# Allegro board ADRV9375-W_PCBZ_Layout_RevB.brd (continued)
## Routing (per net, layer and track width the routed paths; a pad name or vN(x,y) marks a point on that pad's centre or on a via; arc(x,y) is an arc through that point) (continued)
SPI_CLK: length 112.3
  TOP w0.254: U405.3 120.14,60.64 121.68,59.1 121.68,58.09 120.48,56.9 TP802.1 ; U101.K9 v6(36.44,48.38)
  TOP w0.305: R804.1 131.17,56.17 129.9,54.91 121.34,54.91 TP802.1
  L7_SIG w0.114: v8(92.85,57.96) 93.1,58.21 100.72,58.21 104.66,54.28 119,54.28 TP802.1
  L8_SIG w0.114: v6(36.44,48.38) 36.69,48.38 37.08,47.99 41.22,47.99 41.41,48.18 46,48.18 47.19,49.37 49.84,49.37 50.68,50.21 65.67,50.21 73.42,57.96 v8(92.85,57.96)
SPI_CLK_9528: length 44.4
  TOP w0.203: v1(119.77,66.09) 120.14,66.45 U405.12
  L7_SIG w0.114: v1(119.77,66.09) 119.35,66.51 119.35,66.51 119.05,66.81 119.05,66.81 119.01,66.85 118.75,66.85 116.28,69.33 96.08,69.33 93.74,71.67 84.47,71.67 83.56,70.76 82.44,70.76 v1(82.21,70.99)
  BOTTOM w0.254: U401.22 83.47,70.83 83.38,70.74 82.46,70.74 v1(82.21,70.99)
SPI_CS0: length 120.1
  TOP w0.254: v2(139.1,55.57) 138.89,55.57 138.55,55.23 R808.2 R811.1 ; U403.7 116.71,60.56 117.33,59.94 118.65,59.94 119.9,58.69 TP813.1 ; U101.K10 v6(36.44,49.18)
  L7_SIG w0.114: TP813.1 119.34,57.54 116.88,57.54 115.13,55.8 105.67,55.8 101.86,59.61 89.42,59.61 v8(89.04,59.23)
  L8_SIG w0.114: v8(89.04,59.23) 86.37,59.23 85.35,60.24 72.27,60.24 63.89,51.86 46.85,51.86 45.2,50.21 43.9,50.21 43.61,49.93 43.27,49.93 43.11,50.08 40.52,50.08 40.01,49.58 36.84,49.58 v6(36.44,49.18)
  L8_SIG w0.254: TP813.1 122.99,56.18 138.49,56.18 v2(139.1,55.57)
SPI_CS1: length 37
  TOP w0.254: 121.44,63.18 U405.5 ; 117.48,64.82 117.21,64.54 U403.1
  TOP w0.305: R812.1 R809.2 138.55,52.71 138.21,52.37 137.5,52.37 137.12,52.75 137.12,62.12 136.69,62.56 130.74,62.56 130.41,62.23 127.52,62.23 127.34,62.4 TP814.1 124.09,63.67 121.93,63.67 121.44,63.18 119.58,65.03 117.7,65.03 117.48,64.82
SPI_CS_9528: length 47
  TOP w0.203: v1(121.68,65.83) 121.44,66.07 U405.10
  L7_SIG w0.114: v1(121.68,65.83) 121.04,65.2 118.75,65.2 115.77,68.18 95.2,68.18 93.12,70.25 v1(81.7,70.25)
  BOTTOM w0.254: U401.21 83.78,70.33 83.69,70.33 83.62,70.25 v1(81.7,70.25)
SPI_DIN: length 114.3
  TOP w0.254: TP801.1 123,58.66 120.79,60.88 U405.4 ; U101.J9 v6(35.64,48.38)
  TOP w0.305: TP801.1 125.39,56.68 129.45,56.68 130.14,57.37 R805.1
  L7_SIG w0.114: TP801.1 122.03,60.03 117.4,60.03 113.93,56.56 106.18,56.56 102.24,60.5 96.97,60.5 96.59,60.88 87.6,60.88 87.6,60.89 87.17,60.89 87.17,60.88 85.56,60.88 84.03,59.36 v1(83.96,59.36)
  L8_SIG w0.114: v6(35.64,48.38) 36.03,48.76 40.34,48.76 40.95,49.37 45.27,49.37 47,51.1 64.65,51.1 72.96,59.4 83.91,59.4 v1(83.96,59.36)
SPI_DIN_9528: length 43.6
  TOP w0.203: U405.11 v1(120.79,66.34)
  L7_SIG w0.114: v1(83.28,71.33) 85.02,73.07 93.86,73.07 96.53,70.4 116.85,70.4 120.79,66.47 v1(120.79,66.34)
  BOTTOM w0.254: U401.23 83.68,71.33 v1(83.28,71.33)
SPI_DOUT: length 31.6
  TOP w0.203: TP809.1 117.59,58.69 ; 116.2,61.33 U403.6
  TOP w0.254: R806.1 136.06,55.72 136.06,55.71 136.06,55.45 135.47,54.86 130.95,54.86 130.23,54.15 119.47,54.15 118.66,54.96 118.66,57.62 116.19,60.09 116.19,61.32 116.21,61.35 U403.3
SPI_DOUT_9370: length 91.9
  TOP w0.254: U101.J10 v6(35.64,49.18) ; TP402.1 116.07,57.26 R427.2
  L7_SIG w0.097: 39.89,46.39 39.49,46.39
  L7_SIG w0.114: v1(79.64,50.08) 79.64,49.81 77.63,47.8 77.1,47.8 75.41,46.11 48.61,46.11 48.52,46.19 45.18,46.19 44.45,46.92 43.41,46.92 42.88,46.39 39.89,46.39 ; v6(35.64,49.18) 35.64,49.13 36.1,48.66 36.1,48.24 36.3,48.04 36.55,48.04 36.85,47.74 36.85,47.42 37.08,47.19 37.58,47.19 37.7,47.06 37.7,46.64 37.95,46.39 39.49,46.39
  BOTTOM w0.394: TP402.1 111.83,50.08 v1(79.64,50.08)
SPI_DOUT_9528: length 40.5
  TOP w0.254: TP401.1 101.36,71.17 111.83,71.17 R426.2
  L7_SIG w0.114: v1(82.56,71.65) 85.25,74.34 94.12,74.34 96.91,71.55 TP401.1
  BOTTOM w0.254: v1(82.56,71.65) 82.83,71.91 83.59,71.91 83.67,71.83 83.81,71.83 U401.24
STATUS_0: length 25.1
  L5_SIG w0.114: v1(96.53,79.96) 96.19,80.3 77.85,80.3 v1(77.25,79.7)
  BOTTOM w0.254: v1(96.53,79.96) 95.9,79.32 95.9,78.92 94.81,77.83 U401.55 ; R418.1 97.17,79.96
  BOTTOM w0.305: U402.1 76.63,79.69 76.64,79.7 v1(77.25,79.7)
  BOTTOM w0.394: 97.17,79.96 v1(96.53,79.96)
STATUS_1: length 24.5
  L5_SIG w0.114: v1(96.53,78.89) 77.76,78.89 v1(77.25,78.38)
  BOTTOM w0.203: R419.1 97.17,78.89
  BOTTOM w0.254: v1(96.53,78.89) 96.53,78.83 95.03,77.33 U401.56
  BOTTOM w0.305: U402.3 76.63,78.39 76.64,78.38 v1(77.25,78.38)
  BOTTOM w0.394: 97.17,78.89 v1(96.53,78.89)
SYNCINB0+: length 150.5
  TOP w0.254: U101.M4 v6(38.04,43.58)
  L7_SIG w0.091: v2(136.56,61.85) 137.02,61.39 143.14,61.39 143.75,60.77 143.75,42.43 141.97,40.65 141.36,40.65 139.91,39.2 139.91,36.09 137.78,33.96 136.77,33.96 132.45,29.64 127.77,29.64 127.14,29 ; v6(38.04,43.58) 38.04,43.25 37.71,42.91 37.71,41.85 37.93,41.62 39.84,41.62 40.77,40.68 44.84,40.68 48.14,37.38 59.68,37.38 60.57,38.27 105.19,38.27 110.14,33.32 111.79,33.32 113.19,31.92 116.24,31.92 119.66,28.49 126.63,28.49 127.14,29 ; TP807.1 127.14,29
  BOTTOM w0.203: P801.G9 v2(136.56,61.85)
SYNCINB0-: length 150.5
  TOP w0.254: U101.M3 v6(38.04,42.78)
  L7_SIG w0.091: TP808.1 126.14,29.99 126.89,29.24 127.02,29.24 ; 127.02,29.24 127.67,29.89 132.34,29.89 136.66,34.21 137.68,34.21 139.66,36.19 139.66,39.31 141.26,40.91 141.87,40.91 143.5,42.54 143.5,60.67 143.03,61.14 136.92,61.14 136.66,61.39 135.9,61.39 135.77,61.26 135.77,60.58 135.9,60.45 136.44,60.45 136.56,60.58 v2(136.56,60.58) ; 127.02,29.24 126.96,29.18 126.96,29.18 126.52,28.75 119.77,28.75 116.34,32.18 113.29,32.18 111.9,33.57 110.25,33.57 105.29,38.53 60.46,38.53 59.57,37.64 48.25,37.64 44.95,40.94 40.87,40.94 40.09,41.72 40.09,42.16 39.93,42.32 38.14,42.32 38.04,42.42 v6(38.04,42.78)
  BOTTOM w0.203: P801.G10 v2(136.56,60.58)
SYNCINB1+: length 108.7
  TOP w0.254: U101.L4 v6(37.24,43.58)
  L7_SIG w0.091: v6(37.24,43.58) 37.33,43.66 37.33,43.78 37.66,44.12 37.66,44.46 37.9,44.7 38.17,44.7 38.36,44.51 38.36,44.24 38.62,43.98 39.77,43.98 40.01,43.73 44.05,43.73 46.08,41.7 48.4,41.7 49.54,40.56 105.28,40.56 108.88,36.96 109.02,36.96 111.01,34.97 113.4,34.97 114.54,33.83 115.71,33.83 116.02,34.14 ; 116.02,34.14 116.02,34.28 TP810.1 ; 116.02,34.14 121.19,39.32 124.82,39.32 125.02,39.12 125.79,39.12 126.42,39.75 134.79,39.75 v2(135.29,40.26)
  BOTTOM w0.203: P801.G27 v2(135.29,40.26)
SYNCINB1-: length 108.8
  TOP w0.254: U101.L3 v6(37.24,42.78)
  L7_SIG w0.091: 116.84,34.6 115.81,33.57 114.44,33.57 113.29,34.72 110.9,34.72 108.92,36.7 108.78,36.7 105.18,40.31 49.43,40.31 48.29,41.45 45.98,41.45 43.95,43.48 40.01,43.48 39.76,43.23 38.73,43.23 38.51,43.44 38.51,43.56 38.17,43.9 37.8,43.9 37.58,43.68 37.58,43.46 37.56,43.44 37.56,43.44 37.24,43.12 v6(37.24,42.78) ; 116.84,34.6 121.3,39.06 124.71,39.06 124.91,38.86 125.9,38.86 126.53,39.5 134.79,39.5 v2(135.29,38.99) ; 116.84,34.6 117.55,33.89 TP811.1
  BOTTOM w0.203: P801.G28 v2(135.29,38.99)
SYNCOUTB0+: length 115.2
  TOP w0.203: U101.M13 v6(37.24,51.58)
  L8_SIG w0.091: v2(134.02,65.67) 133.55,65.2 127.9,65.2 ; v6(37.24,51.58) 37.38,51.58 37.54,51.74 37.54,52.05 37.78,52.29 38.42,52.29 38.72,51.99 39.88,51.99 40.19,51.68 44.15,51.68 45.86,53.39 51.57,53.39 58.56,60.37 70.39,60.37 71.64,61.62 71.64,66.21 76.08,70.66 76.08,71.42 77.23,72.56 84.34,72.56 86.75,70.15 120.53,70.15 125.49,65.2 127.9,65.2 ; 127.9,65.2 127.9,66.26 TP805.1
  BOTTOM w0.203: P801.H7 134.02,65.66 v2(134.02,65.67)
SYNCOUTB0-: length 115.3
  TOP w0.203: U101.M14 v6(38.04,51.58)
  L8_SIG w0.091: 127.9,64.94 127.9,63.79 TP806.1 ; 127.9,64.94 133.43,64.94 v2(134.02,64.35) ; 127.9,64.94 125.38,64.94 120.43,69.9 86.64,69.9 84.23,72.31 77.33,72.31 76.34,71.32 76.34,70.55 71.89,66.11 71.89,61.51 70.49,60.12 58.66,60.12 51.68,53.13 45.96,53.13 44.26,51.43 40.14,51.43 39.94,51.23 38.67,51.23 38.46,51.43 38.46,51.88 38.32,52.03 37.89,52.03 37.8,51.94 37.8,51.74 37.96,51.58 v6(38.04,51.58)
  BOTTOM w0.203: v2(134.02,64.35) 134.06,64.35 P801.H8
SYSREF_IN+: length 78.5
  TOP w0.254: U101.K3 v6(36.44,42.78)
  L7_SIG w0.091: v1(75.02,75.37) 75.3,75.65 75.56,75.65 75.83,75.38 75.83,74.7 75.47,74.34 73.33,74.34 72.29,73.31 72.29,73.09 70.11,70.91 66.02,70.91 64.62,69.52 59.59,69.52 58.32,68.25 48.9,68.25 46.75,66.09 46.75,65.57 43.19,62.02 43.19,58.7 41.05,56.56 39.87,56.56 37.58,54.28 35.7,54.28 32.65,51.23 32.65,50.47 32.91,50.2 32.91,49.84 33.1,49.65 33.34,49.65 33.71,49.28 33.71,49.07 33.9,48.88 34.23,48.88 34.51,48.6 34.51,45.74 34.68,45.57 34.68,43.95 35.38,43.25 35.96,43.25 v6(36.44,42.78)
  BOTTOM w0.203: 80.57,75.6 75.25,75.6 v1(75.02,75.37) ; 80.57,75.6 R424.2 ; 80.57,75.6 81.12,75.6 82.81,73.9 83.61,73.9 83.68,73.83 84.06,73.83 U401.28
SYSREF_IN-: length 78.7
  TOP w0.254: U101.K4 v6(36.44,43.58)
  L7_SIG w0.091: v6(36.44,43.58) 36.44,43.82 36.36,43.9 35.09,43.9 34.93,44.06 34.93,45.51 35.19,45.77 35.19,48.49 34.97,48.7 34.77,48.7 34.36,49.11 34.36,49.34 34.17,49.53 33.94,49.53 33.56,49.91 33.56,50.11 33.37,50.3 33.17,50.3 32.9,50.57 32.9,51.12 35.8,54.02 37.69,54.02 39.98,56.31 41.16,56.31 43.44,58.59 43.44,61.91 47,65.47 47,65.98 49.01,67.99 58.43,67.99 59.7,69.26 64.73,69.26 66.12,70.66 70.22,70.66 72.55,72.99 72.55,73.2 73.43,74.09 75.57,74.09 76.08,74.6 76.08,75.48 75.67,75.9 75.3,75.9 v1(75.02,76.18)
  BOTTOM w0.203: R424.1 80.57,75.95 ; 80.57,75.95 81.27,75.95 82.96,74.26 83.58,74.26 83.66,74.33 84.12,74.33 U401.29 ; 80.57,75.95 75.25,75.95 v1(75.02,76.18)
TEST: length 169
  TOP w0.254: U101.J6 v6(35.64,45.98)
  TOP w0.394: R504.1 R503.2 143.55,24.35 144.95,25.75 144.95,33.16 143.61,34.5 143.61,40.79 142.12,42.27 142.12,43.33 140.98,44.48 140.98,51.16 142.34,52.52 142.34,58.59 v2(141.62,59.31) 141.31,59.61 R810.1
  L7_SIG w0.114: v6(35.64,45.98) 35.97,45.64 37.47,45.64 37.73,45.89 38.44,45.89 38.7,45.64 45.73,45.64 46.87,44.5 51.55,44.5 51.68,44.63 53.22,44.63 53.86,43.99 54.49,43.99 54.5,44 76.11,44 79.44,47.32 79.8,47.32 82.56,50.08 82.56,51.97 83.34,52.75 84.21,52.75 85.13,53.67 85.13,54.55 86.26,55.67 87.64,55.67 89,57.03 100.63,57.03 104.15,53.51 121.76,53.51 127.39,59.15 133.31,59.15 133.67,58.79 141.1,58.79 v2(141.62,59.31)
TRI_STATE: length 5.4
  BOTTOM w0.394: R408.1 R409.2 122.29,73.9 122.22,73.96 Y402.2 Y401.2
TX1_ENABLE: length 58.8
  TOP w0.254: U101.M6 v6(38.04,45.18)
  TOP w0.305: P501.9 73.61,65.01 R507.1
  L5_SIG w0.114: v6(38.04,45.18) 37.7,45.51 37.22,45.51 36.77,45.96 36.77,46.95 36.49,47.24 36.3,47.24 36.1,47.44 36.1,51.72 36.39,52 36.58,52 36.77,52.2 36.77,52.52 36.65,52.64 36.65,53.7 37.54,54.59 39.7,54.59 40.56,55.45 40.56,55.45 41.73,56.63 43.58,56.63 44.06,57.1 44.48,57.1 44.74,56.85 69.51,56.85 72.53,59.86 72.53,63.8 P501.9
  BOTTOM w0.203: 73.67,66.42 P501.9
TX2_ENABLE: length 53
  TOP w0.254: U101.M8 v6(38.04,47.58)
  TOP w0.305: R506.1 73.73,62.34 P501.10
  L5_SIG w0.114: v6(38.04,47.58) 37.79,47.58 37.37,47.99 37.08,47.99 36.84,48.23 36.84,51.65 37.1,51.91 37.11,51.91 37.22,52.03 37.22,52.69 37.14,52.78 37.14,53.59 37.69,54.14 40.13,54.14 41.16,55.16 44.46,55.16 44.84,55.55 68.97,55.55 73.67,60.24 P501.10
  BOTTOM w0.203: 73.67,60.93 P501.10
TX_EXTLO+: length 12
  TOP w0.203: U101.E12 v6(32.44,49.98)
  L10_SIG w0.091: v6(32.44,49.98) arc(31.87,50.21) 31.64,50.78 arc(31.58,51.07) 31.41,51.32 31.27,51.47 arc(31.23,51.52) 31.22,51.58 arc(31.11,51.85) 30.84,51.96 30.71,51.96 arc(30.61,51.98) 30.51,52.04 arc(30.31,52.3) 30.18,52.59 arc(29.85,53.93) 29.71,55.29 arc(29.6,56.43) 29.37,57.55 arc(29.32,57.79) 29.31,58.05 arc(29.28,58.49) 29.17,58.91 arc(29.1,59.21) v5(29.14,59.52)
  BOTTOM w0.203: C336.2 v5(29.14,59.52)
TX_EXTLO-: length 11.9
  TOP w0.203: U101.E11 v6(31.64,49.98)
  L10_SIG w0.091: v6(31.64,49.98) 31.5,49.98 arc(31.42,50.01) 31.39,50.08 31.38,50.77 arc(31.38,50.77) 31.38,50.78 arc(31.34,50.97) 31.23,51.14 31.21,51.16 arc(31.16,51.19) 31.11,51.2 30.82,51.2 arc(30.59,51.3) 30.49,51.53 arc(30.46,51.69) 30.37,51.83 30.34,51.86 arc(30.1,52.16) 29.93,52.51 arc(29.6,53.88) 29.45,55.28 arc(29.35,56.39) 29.12,57.48 arc(29.07,57.77) 29.06,58.05 arc(29.01,58.58) 28.81,59.07 arc(28.57,59.25) v5(28.28,59.21)
  BOTTOM w0.203: C337.2 v5(28.28,59.21)
UNNAMED_3_CAP_I11_N1: length 11.7
  TOP w0.394: 10.81,55.05 R201.1 ; 10.81,55.05 C200.1 ; 10.81,55.05 9.6,56.26 arc(6.36,58.42) 2.55,59.18 J200.1
UNNAMED_3_CAP_I25_N1: length 12.9
  TOP w0.394: R209.1 C208.1 arc(9.56,36.55) 6.55,35.31 J201.1
UNNAMED_3_CAP_I39_N1: length 6.2
  BOTTOM w0.305: L218.2 23.74,19.6
  BOTTOM w0.394: 23.74,19.6 C217.1 arc(22.87,18.16) 22.58,17.7 arc(22.06,16.48) 21.88,15.16 arc(21.88,14.56) J202.1
UNNAMED_3_CAP_I54_N1: length 18.4
  BOTTOM w0.254: L226.2 16.82,64.82
  BOTTOM w0.394: J203.1 7.95,71.12 arc(12.91,69.69) C225.1 16.82,64.82
UNNAMED_3_CAP_I67_N1: length 17.2
  BOTTOM w0.254: L234.2 16.82,28.59
  BOTTOM w0.394: 16.82,28.59 C233.1 arc(11.47,24.51) 5.98,23.38 arc(3.62,23.37) J204.1
UNNAMED_3_CAP_I109_N1: length 3.1
  TOP w0.203: 20.46,42.45 20.51,42.45 20.72,42.45 20.84,42.45 arc(21.22,42.37) L214.2 ; 20.46,42.45 19.85,42.45 arc(19.25,42.33) T201.5 ; 20.46,42.45 C213.1
UNNAMED_3_CAP_I109_N2: length 3.1
  TOP w0.203: 20.46,42.8 19.91,42.8 arc(19.28,42.92) T201.4 ; 20.46,42.8 20.84,42.8 arc(21.22,42.87) L215.2 ; 20.46,42.8 C213.2
UNNAMED_3_CAP_I141_N1: length 3.1
  BOTTOM w0.203: 22.41,56.15 22.07,56.73 arc(21.88,57.31) T203.5 ; 22.41,56.15 C229.1 ; 22.41,56.15 arc(22.41,56.15) 22.41,56.15 22.51,55.98 22.57,55.87 arc(22.7,55.7) 22.86,55.56 arc(23,55.47) L230.2
UNNAMED_3_CAP_I141_N2: length 3.2
  BOTTOM w0.203: 22.1,55.98 21.99,56.17 21.77,56.55 arc(21.36,57.01) T203.4 ; 22.1,55.98 22.2,55.8 22.26,55.7 arc(22.36,55.46) 22.39,55.2 arc(22.38,55.07) L231.2 ; 22.1,55.98 C229.2
UNNAMED_3_CAP_I188_N1: length 3.2
  BOTTOM w0.127: L238.2 22.62,38.25 ; C237.1 22.22,37.18
  BOTTOM w0.203: 22.62,38.25 arc(22.61,37.88) 22.46,37.53 22.28,37.27 arc(22.28,37.27) 22.28,37.27 22.22,37.18 21.9,36.72 arc(21.46,36.3) T204.5
UNNAMED_3_CAP_I188_N2: length 3.2
  BOTTOM w0.127: C237.2 22.57,37.07 ; L239.2 23.37,37.72
  BOTTOM w0.203: T204.4 arc(21.94,35.96) 22.19,36.52 22.57,37.07 22.57,37.07 22.76,37.33 arc(23.02,37.59) 23.37,37.72
UNNAMED_3_CAP_I194_N1: length 4.2
  TOP w0.394: R209.2 C211.1 10.78,42.41 arc(11.03,43.01) 11.63,43.26 C241.1
UNNAMED_3_CAP_I194_N2: length 1.1
  TOP w0.203: 14.42,43.26 14.92,43.26
  TOP w0.394: 14.42,43.26 13.95,43.26 arc(13.87,43.26) C241.2 ; 14.6,43.26 14.6,43.26
UNNAMED_3_CAP_I197_N1: length 2.3
  BOTTOM w0.305: L218.1 24.13,20.28 ; C242.1 25.24,22.12
  BOTTOM w0.394: 24.13,20.28 C219.1 25.24,22.12
UNNAMED_3_CAP_I197_N2: length 1.1
  BOTTOM w0.203: 25.99,23.73 25.83,23.37 ; C242.2 25.59,22.83
  BOTTOM w0.394: 25.59,22.83 25.83,23.37
UNNAMED_3_CAP_I199_N1: length 2.3
  BOTTOM w0.203: 17.1,64.23 17.12,64.19 ; C243.1 17.98,62.23
  BOTTOM w0.394: 17.98,62.23 C227.1 17.12,64.19
UNNAMED_3_CAP_I199_N2: length 1.1
  BOTTOM w0.203: C243.2 18.42,61.43 ; 18.92,60.59 18.73,60.93
  BOTTOM w0.394: 18.42,61.43 18.73,60.93
UNNAMED_3_CAP_I201_N1: length 2.3
  BOTTOM w0.203: C244.1 18.65,30.7
  BOTTOM w0.254: L234.1 17.25,29.11
  BOTTOM w0.394: 17.25,29.11 C235.1 18.65,30.7
UNNAMED_3_CAP_I201_N2: length 2.3
  BOTTOM w0.203: 19.74,32.24 19.51,31.92 T204.3 ; C244.2 19.19,31.42 arc(19.13,31.38) C244.2
  BOTTOM w0.394: 19.19,31.42 19.51,31.92
UNNAMED_3_CAP_I204_N1: length 1.7
  TOP w0.203: C247.2 14.72,41.77 14.69,41.8
  TOP w0.394: C212.1 14.23,41.8 15.38,41.8 T201.2
UNNAMED_3_CAP_I208_N1: length 1.8
  BOTTOM w0.203: C250.2 24.55,24.07 ; 25.12,24.83 T202.2
  BOTTOM w0.394: 25.12,24.83 24.87,24.74 24.55,24.07 24.38,23.71 C220.1
UNNAMED_3_CAP_I212_N1: length 1.8
  BOTTOM w0.203: C249.2 18.47,32.97
  BOTTOM w0.394: T204.2 18.8,33.43 18.15,32.5 C236.1
UNNAMED_3_CAP_I216_N1: length 1.8
  BOTTOM w0.203: C248.2 20.11,61.42
  BOTTOM w0.394: 19.9,62.18 19.83,61.92 20.4,60.93 T203.2
UNNAMED_3_CAP_I223_N1: length 2.2
  TOP w0.203: C245.1 13.11,52.8
  TOP w0.394: R201.2 C202.1 12.51,53.31 arc(12.65,53.18) 12.79,53.04 arc(12.95,52.92) 13.11,52.8
UNNAMED_3_CAP_I223_N2: length 1.1
  TOP w0.203: 14.42,52.75 14.92,52.75 ; C245.2 13.95,52.75
  TOP w0.394: 13.95,52.75 14.42,52.75 ; 14.6,52.76 14.59,52.75
UNNAMED_3_CAP_I224_N2: length 1.7
  TOP w0.203: C246.2 14.66,51.29
  TOP w0.394: T200.2 15.38,51.29 14.23,51.29 C203.2
UNNAMED_3_CAP_I234_N1: length 3.1
  TOP w0.203: 20.46,51.94 20.84,51.94 arc(21.22,51.87) L205.2 ; 20.46,51.94 C204.1 ; 20.46,51.94 20.29,51.94 19.85,51.94 arc(19.25,51.82) T200.5
UNNAMED_3_CAP_I234_N2: length 3.2
  TOP w0.203: 20.53,52.3 20.46,52.3 C204.2 ; 20.53,52.3 arc(20.19,52.3) 19.84,52.3 arc(19.25,52.41) T200.4 ; 20.53,52.3 arc(20.62,52.3) 20.72,52.3 20.84,52.3 arc(21.22,52.37) L206.2
UNNAMED_3_IND_I132_N2: length 3.1
  BOTTOM w0.203: 27.92,28.92 28,29.12 arc(28.26,29.51) L222.2 ; 27.92,28.92 L221.1 ; 27.92,28.92 27.83,28.72 arc(27.83,28.72) 27.83,28.72 27.66,28.37 arc(27.52,27.78) T202.4
UNNAMED_3_IND_I134_N2: length 3.1
  BOTTOM w0.203: L221.2 27.6,29.08 ; 27.6,29.08 27.68,29.26 arc(27.81,29.71) L223.2 ; 27.6,29.08 27.5,28.86 27.34,28.52 arc(26.98,28.03) T202.5
UNNAMED_4_CAP_I388_N1: length 0.9
  BOTTOM w0.203: 22.6,46.43 23.09,46.43 arc(23.28,46.35) C333.1
UNNAMED_4_CAP_I389_N1: length 0.9
  BOTTOM w0.203: 22.6,46.79 23.09,46.79 arc(23.28,46.87) C332.1
UNNAMED_4_CAP_I525_N1: length 2.1
  TOP w0.127: C305.2 35.44,64.94 ; L301.2 35.44,66.85
  TOP w0.394: 35.44,66.85 C323.1 35.44,64.94
UNNAMED_4_CAP_I526_N1: length 13.3
  TOP w0.127: L301.1 35.44,67.48
  TOP w0.203: C324.1 35.43,68.54
  TOP w0.394: 35.44,67.48 35.43,68.54 arc(35.26,71.11) 34.73,73.64 arc(34.15,76.36) 33.94,79.13 arc(33.94,79.82) J305.1
UNNAMED_4_CAP_I531_N1: length 12.4
  TOP w0.127: C329.1 34.23,25.01 34.24,25.01 ; L302.1 34.23,26.07
  TOP w0.394: 34.23,26.07 34.24,25.01 arc(34.4,22.72) 34.87,20.46 arc(35.53,17.25) J306.1
UNNAMED_4_CAP_I533_N1: length 2.1
  TOP w0.127: L302.2 34.23,26.7 ; C306.2 34.23,28.61
  TOP w0.394: 34.23,28.61 C328.1 34.23,26.7
UNNAMED_4_CAP_I561_N1: length 3.6
  BOTTOM w0.203: T307.1 20.56,47.25 C331.1
  BOTTOM w0.394: 19.36,47.24 20.56,47.25 ; 19.36,47.24 C331.1 ; 19.36,47.24 R312.2
UNNAMED_4_CAP_I563_N1: length 16.6
  BOTTOM w0.394: R312.1 C330.1 J307.1
UNNAMED_4_CAP_I600_N2: length 4.6
  TOP w0.203: C339.2 35.73,30.79 T306.2
  TOP w0.508: C322.2 36.14,27.59 C314.2 36.14,28.49 C326.2 35.5,30.03 T306.2
UNNAMED_4_CAP_I601_N1: length 3.7
  BOTTOM w0.203: T308.1 27.93,63.37 C335.1
  BOTTOM w0.394: 27.51,64.54 R313.2 ; 27.51,64.54 C335.1 ; 27.51,64.54 27.93,63.37
UNNAMED_4_CAP_I603_N1: length 15.7
  BOTTOM w0.394: J308.1 21.88,79.08 arc(22.29,77.11) 23.05,75.25 arc(24.76,71.71) 26.22,68.06 C334.1 R313.1
UNNAMED_4_CAP_I646_N2: length 4.8
  TOP w0.203: C338.2 33.94,62.76 T305.2
  TOP w0.394: C321.2 C312.2 C313.2
  TOP w0.508: C321.2 34.17,63.52 T305.2
UNNAMED_4_CAP_I696_N1: length 0.9
  BOTTOM w0.203: 28.2,61.26 28.37,60.81 arc(28.51,60.65) 28.73,60.64
UNNAMED_4_CAP_I697_N1: length 0.9
  BOTTOM w0.203: 27.87,61.14 28.03,60.69 arc(28.03,60.47) C337.1
UNNAMED_5_CAP_I803_N2: length 1
  BOTTOM w0.254: C411.2 89.86,65.58 89.85,65.59 R415.1
UNNAMED_5_CAP_I905_N1: length 6.4
  BOTTOM w0.394: C401.1 105.81,62.02 R401.2 107.27,60.57 J401.1
UNNAMED_5_CAP_I905_N2: length 1.6
  BOTTOM w0.394: T401.4 C401.2
UNNAMED_5_CAP_I916_N1: length 63
  BOTTOM w0.203: R411.2 R413.1 107.96,73.69 107.51,74.14 104.14,74.14 102.65,72.66 102.65,69.23 106.01,65.87 113,65.87 115.6,63.27 115.6,58.11 113.65,56.16 100.87,56.16 96.93,60.09 89.65,60.09 88.43,61.31 88.43,62.04 88.76,62.37 C408.1
UNNAMED_5_CMOSNC7WV125K8X_I90_1: length 3.6
  TOP w0.203: 115.71,61.09 U403.5
  TOP w0.254: R427.1 115.33,60.37 115.71,60.76 115.71,61.09
UNNAMED_5_CMOSNC7WV125K8X_I90_A: length 1.7
  TOP w0.254: R426.1 116.7,64.05 116.71,64.03 U403.2
UNNAMED_5_DIOLED_I865_P: length 2.5
  TOP w0.305: v1(70.24,78.29) 69.91,77.96 D401.A
  BOTTOM w0.305: R420.2 v1(70.24,78.29)
UNNAMED_5_DIOLED_I866_P: length 2.4
  TOP w0.305: D402.A 69.94,80.12 v1(70.24,79.82)
  BOTTOM w0.305: v1(70.24,79.82) R421.2
UNNAMED_5_NC7WZ17P6X_I868_Y1: length 1.9
  BOTTOM w0.305: R421.1 73.01,79.82 73.14,79.69 U402.6
UNNAMED_5_NC7WZ17P6X_I868_Y2: length 1.9
  BOTTOM w0.305: R420.1 73.14,78.29 73.24,78.39 U402.4
UNNAMED_5_RES_I897_N2: length 63
  BOTTOM w0.203: R410.2 R412.2 107.96,70.68 107.62,70.35 105.78,70.35 104.75,71.37 103.45,71.37 103.01,70.93 103.01,69.38 106.16,66.23 113.14,66.23 115.96,63.41 115.96,57.96 113.8,55.8 100.72,55.8 96.78,59.74 89.5,59.74 88.07,61.16 88.07,62.04 87.74,62.37 R414.1
UNNAMED_5_RES_I907_N2: length 1.6
  BOTTOM w0.394: T401.5 R402.2
UNNAMED_6_AD9375_I826_DEVCLKIN: length 1.2
  TOP w0.203: U101.E8 v5(31.64,46.78)
  BOTTOM w0.203: C501.2 31.71,46.95 arc(31.69,46.86) v5(31.64,46.78)
UNNAMED_6_AD9375_I826_DEVCLKIN_: length 1.2
  TOP w0.203: U101.E7 v5(32.44,46.78)
  BOTTOM w0.203: C502.2 32.34,47 arc(32.37,46.88) v5(32.44,46.78)
UNNAMED_6_AD9375_I826_RBIAS: length 2.5
  TOP w0.203: U101.C14 28.89,53.52 R505.2
UNNAMED_6_AD9375_I832_SERDIN0: length 113
  TOP w0.203: U101.P12 v6(39.58,50.71)
  L5_SIG w0.091: v2(147.32,40.64) arc(147.11,40.39) 146.79,40.32 arc(145.37,40.08) 144.28,39.13 143.87,38.51 arc(142.82,37.55) 141.44,37.2 133.67,37.2 arc(127.56,38.1) 121.94,40.66 arc(116.24,43.25) 110.04,44.13 58.08,44.13 arc(50.72,45.39) 44.28,49.16 arc(42.54,50.19) 40.55,50.55 40.19,50.55 arc(39.87,50.59) v6(39.58,50.71)
  BOTTOM w0.203: C508.2 v2(147.32,40.64)
UNNAMED_6_AD9375_I832_SERDIN0_1: length 113.1
  TOP w0.203: U101.P11 v6(39.62,50.05)
  L5_SIG w0.091: v2(147.32,39.88) arc(147.05,40.01) 146.77,40.07 arc(145.48,39.85) 144.49,38.99 144.08,38.37 arc(142.94,37.32) 141.44,36.94 133.67,36.94 arc(127.49,37.86) 121.8,40.45 arc(116.17,43) 110.04,43.88 58.08,43.88 arc(50.63,45.15) 44.12,48.97 arc(42.45,49.95) 40.55,50.29 40.19,50.29 arc(39.88,50.23) v6(39.62,50.05)
  BOTTOM w0.203: C507.2 v2(147.32,39.88)
UNNAMED_6_AD9375_I832_SERDIN1: length 117.1
  TOP w0.203: 142.47,71.57 v6(142.91,72.01) ; v6(39.64,52.38) U101.P14
  L10_SIG w0.091: v6(142.91,72.01) arc(142.75,71.65) 142.39,71.5 140.4,71.5 arc(138.83,71.22) 137.5,70.35 arc(136.05,68.24) 135.29,65.8 arc(134.27,61.98) 132.42,58.48 arc(129.25,55.18) 125.16,53.1 arc(122.26,51.94) 119.56,50.36 arc(115.79,48.51) 111.63,47.87 55.41,47.87 arc(50.97,48.51) 46.85,50.29 arc(43.76,51.63) 40.42,52.09 40,52.09 arc(39.77,52.17) v6(39.64,52.38)
UNNAMED_6_AD9375_I832_SERDIN1_1: length 117
  TOP w0.203: U101.P13 39.63,51.57 v6(39.63,51.64) ; 142.47,70.3 v6(142.91,70.74)
  L10_SIG w0.091: v6(142.91,70.74) arc(142.75,71.1) 142.38,71.25 140.39,71.25 arc(138.93,70.99) 137.69,70.17 arc(136.28,68.13) 135.54,65.76 arc(134.51,61.89) 132.63,58.34 arc(129.4,54.97) 125.23,52.86 arc(122.37,51.71) 119.71,50.15 arc(115.87,48.26) 111.63,47.62 55.41,47.62 arc(50.9,48.26) 46.72,50.08 arc(43.69,51.39) 40.42,51.83 40,51.83 arc(39.79,51.78) v6(39.63,51.64)
UNNAMED_6_AD9375_I832_SERDIN2: length 115.5
  TOP w0.203: v6(38.84,49.98) U101.N11
  L5_SIG w0.091: v2(147.32,35.56) arc(147.19,35.38) 146.98,35.31 146.52,35.31 arc(145.82,35.19) 145.2,34.84 arc(144.38,34.06) 143.62,33.21 arc(142.63,32.42) 141.39,32.14 133.34,32.14 arc(131.14,32.34) 129.02,32.93 arc(124.36,34.99) 119.93,37.51 arc(115.19,39.66) 110.04,40.39 60.44,40.39 arc(50.91,42.41) 43.09,48.22 arc(41.62,49.32) 39.84,49.7 39.15,49.7 arc(38.94,49.78) v6(38.84,49.98)
  BOTTOM w0.203: C512.2 v2(147.32,35.56)
UNNAMED_6_AD9375_I832_SERDIN2_1: length 115.5
  TOP w0.203: v6(38.84,49.18) U101.N10
  L5_SIG w0.091: v6(38.84,49.18) arc(38.94,49.37) 39.15,49.45 39.84,49.45 arc(41.52,49.08) 42.9,48.06 arc(50.8,42.18) 60.44,40.14 110.04,40.14 arc(115.12,39.41) 119.79,37.29 arc(124.24,34.76) 128.93,32.69 arc(131.1,32.09) 133.34,31.89 141.39,31.89 arc(142.74,32.19) 143.82,33.05 arc(144.56,33.88) 145.37,34.64 arc(145.9,34.96) 146.51,35.05 146.98,35.05 arc(147.19,34.98) v2(147.32,34.8)
  BOTTOM w0.203: C511.2 v2(147.32,34.8)
UNNAMED_6_AD9375_I832_SERDIN3: length 114.3
  TOP w0.203: v6(38.84,51.58) U101.N13
  L5_SIG w0.091: v2(147.32,45.72) arc(147.13,45.52) 146.87,45.45 146.49,45.45 arc(145.78,45.29) 145.2,44.84 144.77,44.3 142.97,42.06 arc(140.84,40.37) 138.19,39.76 134.18,39.76 arc(132.37,39.93) 130.62,40.42 arc(127.2,41.96) 123.95,43.81 arc(117.28,46.83) 110.04,47.87 55.54,47.87 arc(51.44,48.34) 47.56,49.75 arc(44.29,50.92) 40.83,51.3 39.26,51.3 arc(39.01,51.38) v6(38.84,51.58)
  BOTTOM w0.203: C514.2 v2(147.32,45.72)
UNNAMED_6_AD9375_I832_SERDIN3_1: length 114.3
  TOP w0.203: v6(38.84,50.78) U101.N12
  L5_SIG w0.091: v2(147.32,44.96) arc(147.2,45.13) 147,45.19 146.86,45.19 146.49,45.19 arc(145.89,45.06) 145.4,44.68 144.96,44.14 143.17,41.9 arc(140.95,40.14) 138.19,39.51 134.18,39.51 arc(132.32,39.68) 130.53,40.19 arc(127.09,41.73) 123.81,43.6 arc(117.21,46.59) 110.04,47.62 55.54,47.62 arc(51.38,48.1) 47.45,49.52 arc(44.23,50.67) 40.83,51.05 39.26,51.05 arc(39.01,50.97) v6(38.84,50.78)
  BOTTOM w0.203: C513.2 v2(147.32,44.96)
UNNAMED_6_AD9375_I832_SERDOUT0: length 123.3
  TOP w0.203: U101.P7 v6(39.56,46.05)
  L10_SIG w0.091: v2(147.32,71.12) arc(147.19,70.93) 146.98,70.85 146.7,70.85 arc(144.61,70.34) 143.04,68.87 arc(141.64,67.23) 139.84,66.05 arc(137.86,64.32) 137.12,61.79 137.12,54.15 arc(136.63,52.96) 135.45,52.47 133.77,52.47 arc(126.65,51.45) 120.11,48.47 arc(116.05,46.63) 111.63,46 55.5,46 arc(52.96,46.04) 50.42,45.99 arc(45.35,45.83) 40.28,45.78 40.05,45.78 arc(39.77,45.85) v6(39.56,46.05)
  BOTTOM w0.203: C516.2 v2(147.32,71.12)
UNNAMED_6_AD9375_I832_SERDOUT0_: length 123.3
  TOP w0.203: U101.P6 v6(39.56,45.25)
  L10_SIG w0.091: v2(147.32,70.36) arc(147.2,70.54) 146.99,70.6 146.98,70.6 146.69,70.6 arc(144.73,70.12) 143.25,68.74 arc(141.81,67.04) 139.95,65.82 arc(138.07,64.18) 137.38,61.79 137.38,54.15 arc(136.81,52.78) 135.45,52.22 133.77,52.22 arc(126.72,51.2) 120.25,48.26 arc(116.12,46.39) 111.63,45.75 55.49,45.75 arc(52.96,45.79) 50.43,45.73 arc(45.36,45.58) 40.28,45.53 40.05,45.53 arc(39.77,45.45) v6(39.56,45.25)
  BOTTOM w0.203: C515.2 v2(147.32,70.36)
UNNAMED_6_AD9375_I832_SERDOUT1: length 127
  TOP w0.203: U101.P5 v6(39.7,44.32)
  L10_SIG w0.091: v6(39.7,44.32) 39.8,44.23 arc(39.96,44.12) 40.15,44.08 41.05,44.08 arc(47.4,43.31) 53.37,41.03 arc(58.24,39.17) 63.41,38.52 111.63,38.52 arc(120.66,40.32) 128.31,45.43 arc(130.63,46.95) 133.36,47.41 139.13,47.41 140.77,47.77 140.97,47.96 140.97,48.14 141.38,48.55 141.97,48.55 142.06,48.46 142.15,48.46 142.88,49.14 142.92,49.19 143.16,50.03 143.37,50.23 143.37,50.72 143.59,51.49 143.59,59.14 arc(144.28,62.59) 146.24,65.49 146.3,65.55 arc(146.6,65.75) 146.95,65.82 arc(147.16,65.89) v2(147.32,66.04)
  BOTTOM w0.203: C518.2 v2(147.32,66.04)
UNNAMED_6_AD9375_I832_SERDOUT1_: length 127
  TOP w0.203: U101.P4 v6(39.56,43.65)
  L10_SIG w0.091: v6(39.56,43.65) arc(39.75,43.78) 39.98,43.83 41.05,43.83 arc(47.34,43.06) 53.25,40.81 arc(58.18,38.92) 63.41,38.27 111.63,38.27 arc(120.75,40.08) 128.49,45.25 arc(130.72,46.71) 133.35,47.16 139.16,47.16 140.9,47.54 141.22,47.86 141.22,48.03 141.49,48.3 141.86,48.3 141.95,48.21 142.25,48.21 143.07,48.97 143.14,49.05 arc(143.14,49.06) 143.15,49.08 arc(143.67,50.21) 143.84,51.45 143.84,59.14 arc(144.51,62.49) 146.42,65.31 146.42,65.31 146.48,65.38 arc(146.7,65.52) 146.95,65.57 146.96,65.57 arc(147.2,65.49) v2(147.32,65.28)
  BOTTOM w0.203: C517.2 v2(147.32,65.28)
UNNAMED_6_AD9375_I832_SERDOUT2: length 119.9
  TOP w0.203: 142.47,64.83 v6(142.91,64.39)
  TOP w0.254: v6(38.84,45.18) U101.N6
  L10_SIG w0.091: v6(38.84,45.18) arc(38.84,44.99) 39,44.9 41.89,44.9 arc(47.07,44.58) 52.16,43.62 arc(57.67,42.59) 63.26,42.26 111.63,42.26 arc(117.94,43.31) 123.57,46.34 arc(128.49,48.99) 134,49.91 136.94,49.91 arc(138.78,50.21) 140.42,51.07 arc(141.69,52.58) 142.15,54.5 142.15,61.46 arc(142.11,61.87) 141.98,62.26 141.77,62.73 arc(141.7,62.97) 141.68,63.22 arc(141.92,63.77) 142.49,63.96 arc(142.81,64.07) v6(142.91,64.39)
UNNAMED_6_AD9375_I832_SERDOUT2_: length 119.9
  TOP w0.203: 142.47,63.56 v6(142.91,63.12)
  TOP w0.254: v6(38.84,44.38) U101.N5
  L10_SIG w0.091: v6(142.91,63.12) arc(142.82,63.51) 142.47,63.71 arc(142.09,63.58) 141.93,63.22 arc(141.95,63.02) 142.01,62.83 142.21,62.36 arc(142.36,61.92) 142.4,61.46 142.4,54.5 arc(141.92,52.46) 140.58,50.86 arc(138.86,49.97) 136.95,49.65 134,49.65 arc(128.57,48.75) 123.73,46.14 arc(118.02,43.07) 111.63,42.01 63.26,42.01 arc(57.63,42.34) 52.1,43.38 arc(47.03,44.33) 41.89,44.65 39.25,44.65 arc(39.01,44.57) v6(38.84,44.38)
UNNAMED_6_AD9375_I832_SERDOUT3: length 127.4
  TOP w0.254: v6(38.84,43.58) U101.N4
  L10_SIG w0.091: v2(147.32,60.96) arc(147.17,60.8) 146.97,60.72 arc(145.49,59.87) 144.91,58.27 144.91,46.7 arc(144.36,45.37) 143.03,44.82 133.57,44.82 arc(130.67,44.33) 128.13,42.84 arc(120.44,38.25) 111.63,36.65 61.58,36.65 arc(55.3,37.57) 49.64,40.45 arc(45.52,42.57) 40.95,43.3 39.05,43.3 arc(38.88,43.39) v6(38.84,43.58)
  BOTTOM w0.203: C522.2 v2(147.32,60.96)
UNNAMED_6_AD9375_I832_SERDOUT3_: length 127.4
  TOP w0.254: v6(38.84,42.78) U101.N3
  L10_SIG w0.091: v2(147.32,60.2) arc(147.24,60.41) 147.02,60.47 arc(145.69,59.71) 145.16,58.27 145.16,46.7 arc(144.54,45.19) 143.03,44.56 133.56,44.56 arc(130.75,44.09) 128.3,42.64 arc(120.53,38.01) 111.63,36.4 61.58,36.4 arc(55.22,37.33) 49.49,40.25 arc(45.45,42.33) 40.95,43.05 39.36,43.05 arc(39.06,42.98) v6(38.84,42.78)
  BOTTOM w0.203: C521.2 v2(147.32,60.2)
UNNAMED_6_CN20PV2_I813_N6: length 4.1
  TOP w0.394: P504.11 49.82,72.47 TP502.1
UNNAMED_6_CN20PV2_I813_N7: length 3.7
  TOP w0.394: TP501.1 51.09,71.39 P504.13
UNNAMED_6_CN20PV2_I813_N9: length 2.4
  TOP w0.394: R525.2 P504.17
UNNAMED_6_CN20PV2_I814_N1: length 71.8
  TOP w0.305: v1(88.06,49.41) 87.96,49.31 87.68,49.31 87.6,49.23 R519.2
  TOP w0.394: P504.2 v1(43.47,80.51)
  L10_SIG w0.114: v1(43.47,80.51) 44.04,81.07 44.98,81.07 45.4,80.64 45.4,80.2 49.92,75.68 49.92,62.02 51.95,59.99 77.73,59.99 82.2,55.52 86.6,55.52 87.47,54.64 87.47,50 v1(88.06,49.41)
UNNAMED_6_CN20PV2_I814_N2: length 70.4
  TOP w0.203: R521.2 74.05,57.64 75.76,57.64 77.48,55.93 v1(79.83,55.93) 82.94,55.93 84.02,57 R520.2
  TOP w0.394: P504.4 v1(44.74,80.47)
  L10_SIG w0.114: v1(44.74,80.47) 44.74,79.9 46.55,78.09 46.55,64.11 46.55,64.11 46.55,63.68 46.55,63.68 46.55,63.49 50.56,59.48 74.69,59.48 78.24,55.93 v1(79.83,55.93)
UNNAMED_6_CN20PV2_I814_N3: length 68.8
  TOP w0.305: v1(90.43,49.43) 90.41,49.43 90.3,49.31 90.22,49.31 90.14,49.23 89.67,49.23
  TOP w0.394: P504.6 v1(46.01,80.51)
  L10_SIG w0.114: v1(90.43,49.43) 90.06,49.8 90.06,54.4 88.29,56.18 83.45,56.18 79.01,60.62 56.53,60.62 55.13,62.02 55.13,65.83 53.86,67.1 53.86,73.45 47.51,79.8 46.71,79.8 v1(46.01,80.51)
UNNAMED_6_CN20PV2_I814_N4: length 56.5
  TOP w0.203: v1(87.39,60.37) 87.39,58.43 R523.2
  TOP w0.394: P504.8 v1(47.28,80.51)
  L10_SIG w0.114: v1(87.39,60.37) 81.75,60.37 80.02,62.1 80.02,65.58 77.63,67.97 62.26,67.97 49.73,80.51 v1(47.28,80.51)
UNNAMED_6_CN20PV2_I814_N8: length 52
  TOP w0.203: R524.2 91.29,58.75 85.99,64.05 v1(85.99,64.56)
  TOP w0.394: P504.16 v1(52.36,80.51)
  L10_SIG w0.114: v1(52.36,80.51) 59.8,73.07 69.61,73.07 72.78,69.9 78.24,69.9 82.05,66.09 84.46,66.09 v1(85.99,64.56)
UNNAMED_7_AD7291_I1067_DCAP: length 2.6
  TOP w0.305: C651.1 44.46,22.91 45.35,22.91 45.73,23.29 U601.8
UNNAMED_7_AD7291_I1067_VIN0: length 5.2
  TOP w0.305: U601.18 51.2,23.29 51.58,22.91 52.09,22.91 R603.1 R602.1
UNNAMED_7_AD7291_I1067_VIN1: length 4.5
  TOP w0.305: U601.19 52.88,23.79 52.89,23.8 53.48,23.8 ; 53.48,23.8 R604.2 ; 53.48,23.8 R605.2
UNNAMED_7_AD7291_I1067_VIN2: length 5.2
  TOP w0.305: U601.20 50.79,24.29 51.19,24.69 52.09,24.69 R606.2 R607.2
UNNAMED_7_AD7291_I1067_VIN3: length 4.6
  TOP w0.305: R609.2 R608.2 50.43,26.98 49.52,26.06 U601.1
UNNAMED_7_AD7291_I1067_VIN5: length 4.4
  TOP w0.305: U601.3 48.52,26.46 48.91,26.85 R611.2 R610.2
UNNAMED_7_AD7291_I1067_VIN7: length 4.9
  TOP w0.305: R612.2 R613.2 47.52,26.33 U601.5
UNNAMED_7_AD7291_I1067_VREF: length 2.3
  TOP w0.305: C650.1 45.01,23.92 45.6,23.92 45.74,23.79 U601.7
UNNAMED_7_AD9375_I936_VCLKVCOLD: length 1.2
  TOP w0.254: v2(38.04,41.18) U101.M1
  BOTTOM w0.305: C644.1 38.06,41.2 v2(38.04,41.18)
UNNAMED_7_AD9375_I936_VDDABB: length 10.6
  TOP w0.254: v2(31.64,44.38) U101.E5
  L12_PWR w0.394: v3(33.41,39.7) v3(33.41,40.31) v3(33.03,40.69) 31.38,42.34 31.38,44.12 v2(31.64,44.38)
  BOTTOM w0.305: C606.1 31.99,44.36 v2(31.64,44.38)
  BOTTOM w0.394: v3(33.03,40.69) v3(33.41,40.31) v3(33.41,39.7)
  BOTTOM w0.508: C604.1 31.25,43.99 v2(31.64,44.38) ; R614.1 33.7,39.4 v3(33.41,39.7)
UNNAMED_7_AD9375_I936_VDDARXRF: length 7.6
  TOP w0.254: U101.B1 v2(29.24,41.18)
  L12_PWR w0.394: v4(28.71,35.73) 28.1,36.34 28.1,36.9 28.71,37.51 v3(28.71,38.76)
  BOTTOM w0.305: v2(29.24,41.18) 29.23,41.17 C605.1
  BOTTOM w0.394: v3(28.71,38.76) 28.71,39.28 C603.1 28.9,40.23 C605.1 ; R615.1 v4(28.71,35.73)
UNNAMED_7_AD9375_I936_VRXVCOLDO: length 1.2
  TOP w0.254: U101.C8 v2(30.04,46.78)
  BOTTOM w0.305: v2(30.04,46.78) 30.03,46.78 C645.1
UNNAMED_7_AD9375_I936_VSNRXVCOL: length 0.8
  TOP w0.254: v2(30.04,42.78) U101.C3
  BOTTOM w0.508: v2(30.04,42.78) 30.04,42.78 C646.1
UNNAMED_7_AD9375_I936_VTXVCOLDO: length 14.5
  TOP w0.254: U101.F13 v6(32.44,51.58)
  L10_SIG w0.305: 33.64,52.31 33.24,51.91 32.78,51.91 v6(32.44,51.58)
  L10_SIG w0.508: 33.64,52.31 34.05,52.71 34.05,57.7 38.12,61.78 v1(38.49,61.78)
  BOTTOM w0.394: v1(38.49,61.78) C647.1
UNNAMED_8_ADP125_I911_ADJ: length 3.1
  TOP w0.254: U702.3 50.34,15.34 R739.1 R740.2
UNNAMED_8_ADP5054_I118_BST1: length 2
  TOP w0.394: v1(83.45,26.62) 83.46,26.61 C713.1
  BOTTOM w0.203: U701.32 v1(83.45,26.62)
UNNAMED_8_ADP5054_I118_BST2: length 1.9
  TOP w0.394: v1(83.56,24.62) 83.58,24.6 C715.2
  BOTTOM w0.254: U701.28 v1(83.56,24.62)
UNNAMED_8_ADP5054_I118_BST3: length 2
  TOP w0.394: C717.1 92.53,28.75 v1(92.4,28.62)
  BOTTOM w0.254: U701.1 v1(92.4,28.62)
UNNAMED_8_ADP5054_I118_BST4: length 1.7
  BOTTOM w0.254: U701.12 92.86,23.12 C719.1
UNNAMED_8_ADP5054_I118_COMP1: length 2.8
  BOTTOM w0.254: U701.40 86.75,30.08 86.74,30.09 86.74,30.88 87.62,31.76 R704.2
UNNAMED_8_ADP5054_I118_COMP2: length 2.2
  BOTTOM w0.254: R707.2 86.63,20.66 87.25,21.28 U701.20
UNNAMED_8_ADP5054_I118_COMP3: length 2.8
  BOTTOM w0.203: R708.2 90.94,31.7 90.94,30.56 90.27,29.89 90.27,29.85 90.25,29.83 U701.47
UNNAMED_8_ADP5054_I118_COMP4: length 2.1
  BOTTOM w0.254: R711.2 90,20.87 89.75,21.12 U701.15
UNNAMED_8_ADP5054_I118_DL1: length 5.3
  TOP w0.394: R718.2 82.31,24.22 v1(82.33,24.19)
  BOTTOM w0.203: v1(82.33,24.19) 82.99,24.85 82.99,25.76 83.3,26.06 83.94,26.06 83.99,26.12 U701.31
  BOTTOM w0.254: Q701.5 82.31,24.22 v1(82.33,24.19)
UNNAMED_8_ADP5054_I118_DL2: length 8.9
  TOP w0.394: v1(78.55,24.22) 81.17,26.84 R719.2 82.43,26.71 83.55,25.59 v1(83.55,25.46)
  BOTTOM w0.203: U701.29 83.9,25.12 v1(83.55,25.46)
  BOTTOM w0.254: Q701.2 v1(78.55,24.22)
UNNAMED_8_ADP5054_I118_EN1: length 48.1
  L5_SIG w0.394: v1(90.36,21.4) 90.36,21.95 90.81,22.4 92.21,22.4 94.5,24.68 94.5,30.53 93.1,31.92 91.58,31.92 91.07,31.42 91.07,30.91 90.18,30.02 86.69,30.02 v1(85.59,31.13) 84.92,31.79 82.68,31.79 81.23,30.34 72.34,30.34 69.13,33.55 P702.2
  BOTTOM w0.254: U701.14 90.25,21.51 v1(90.36,21.4) 91.03,20.73 C711.2 ; U701.39 86.25,30.46 v1(85.59,31.13) R705.2 R706.1
UNNAMED_8_ADP5054_I118_EN2: length 51.8
  TOP w0.305: R702.2 73.33,32.53 P702.1
  TOP w0.394: v1(86.65,21.5) 86.87,21.29 86.87,20.73 R703.1
  L5_SIG w0.394: v1(86.65,21.5) 86.65,21.04 85.84,20.23 83.12,20.23 80.78,22.57 80.78,23.03 77.1,26.72 69.61,26.72 66.92,29.41 64.58,29.41 63.64,30.35 63.64,34.08 65.8,36.25 69.62,36.25 P702.1
  BOTTOM w0.254: U701.21 86.75,21.6 v1(86.65,21.5)
UNNAMED_8_ADP5054_I118_EN3: length 35.8
  L5_SIG w0.394: v1(91.95,31.03) 91.95,30.14 91.07,29.26 85.73,29.26 84.75,30.24 82.43,30.24 81.45,29.26 71.53,29.26 P702.3
  BOTTOM w0.203: U701.48 90.75,29.44 90.94,29.64 90.94,29.76
  BOTTOM w0.254: P702.3 66.6,34.2 R712.1
  BOTTOM w0.394: C712.2 R710.1 R709.2 v1(91.95,31.03) 91.95,30.77 90.94,29.76
UNNAMED_8_ADP5054_I118_FB1: length 37.9
  TOP w0.394: v1(87.72,31.03) 87.72,31.08 87.72,31.08 87.72,31.94 86.92,32.74 R714.1 R716.1 84.3,34.49 83.91,34.89 83.9,34.89 82.35,36.44 76.21,36.44 74.41,34.63 v1(74.41,34)
  L5_SIG w0.394: v1(87.72,31.03) 87.72,31.03 87.56,31.03 85.78,32.81 75.59,32.81 v1(74.41,34)
  BOTTOM w0.254: v1(87.72,31.03) 87.72,30.88 87.25,30.4 U701.41
  BOTTOM w0.508: v1(74.41,34) R715.1 74.41,32.17 74.05,31.81 R717.1
UNNAMED_8_ADP5054_I118_FB2: length 25.6
  TOP w0.394: R723.1 R720.2 v1(87.59,19.19)
  BOTTOM w0.203: U701.19 87.75,20.59 87.59,20.43 v1(87.59,19.19)
  BOTTOM w0.508: R722.1 74.31,16.27 74.66,15.91 R721.1 74.66,14.62 75.2,14.08 85.64,14.08 87.52,15.96 87.52,19.11 v1(87.59,19.19)
UNNAMED_8_ADP5054_I118_FB3: length 13
  TOP w0.394: v1(96.55,34.1) 96.29,33.85 R727.1 R724.2 92.02,32.87 v1(90.28,31.13)
  BOTTOM w0.203: U701.46 89.75,30.08 90.28,30.62 v1(90.28,31.13)
  BOTTOM w0.508: R726.1 96.91,32.78 97.45,33.31 R725.1 v1(96.55,34.1)
UNNAMED_8_ADP5054_I118_FB4: length 21.3
  TOP w0.394: R731.1 92.43,20.45 R728.2 89.18,20.45 v1(89.17,20.43)
  BOTTOM w0.203: v1(89.17,20.43) 89.25,20.52 U701.16
  BOTTOM w0.254: 89.09,18.4 89.17,18.48 v1(89.17,20.43)
  BOTTOM w0.508: 89.09,18.4 89.09,16.32 90.36,15.05 96.89,15.05 97.42,15.58 R729.1 97.42,17.11 96.91,17.61 R730.1
UNNAMED_8_ADP5054_I118_PWRGD: length 31.5
  L5_SIG w0.508: v1(88.53,19.42) 87.39,20.56 87.39,21.76 86.62,22.53 84.59,22.53 83.63,23.48 81.6,23.48 77.18,27.91 71.05,27.91 67.54,31.42 v1(66.56,31.42)
  BOTTOM w0.203: v1(88.53,19.42) 88.53,20.79 88.75,21.01 U701.17
  BOTTOM w0.394: v1(66.56,31.42) R712.2
UNNAMED_8_ADP5054_I118_RT: length 2.8
  BOTTOM w0.203: R713.1 88.63,31.77 88.28,31.42 88.28,30.8 88.28,30.8 88.28,30.72 87.75,30.19 U701.42
UNNAMED_8_ADP5054_I118_SW11: length 6.4
  TOP w0.394: C713.2 83.53,27.88 v1(83.32,28.08) v1(83.32,27.44)
  BOTTOM w0.254: Q701.PAD2 80,24.68 79.81,24.87 Q701.3 79.6,25.65 79.84,25.9 ; U701.35 83.36,28.12 v1(83.32,28.08) ; U701.33 83.8,27.12 83.48,27.44 v1(83.32,27.44)
UNNAMED_8_ADP5054_I118_SW21: length 6.2
  TOP w0.394: C715.1 82.97,22.44 v1(82.64,22.11) v1(82.64,22.77)
  BOTTOM w0.254: 82.38,23.36 82.17,23.57 Q701.6 ; Q701.PAD1 80.93,23.75 81.11,23.57 Q701.6 ; U701.27 83.89,24.12 83.58,23.81 ; Q701.6 81.42,22.85 ; U701.25 83.86,23.12
UNNAMED_8_ADP5054_I118_SW31: length 4.7
  TOP w0.394: v1(93.13,26.58) v1(93.76,26.58) 93.45,26.9 C717.2
  BOTTOM w0.254: U701.5 93.09,26.62 v1(93.13,26.58) ; U701.4 92.87,27.12
UNNAMED_8_ADP5054_I118_SW41: length 3.3
  BOTTOM w0.254: C719.2 93.07,24.38 ; 93.07,24.38 92.83,24.62 U701.9 ; 93.07,24.38 93.08,24.38 ; U701.8 92.53,25.12 92.9,24.75
UNNAMED_8_ADP5054_I118_VDD: length 2.9
  TOP w0.394: v1(88.89,31.03) 89.22,31.36 C703.2
  BOTTOM w0.203: v1(88.89,31.03) 88.89,30.7 88.25,30.06 U701.43
UNNAMED_8_CAP_I809_N2: length 2.1
  BOTTOM w0.762: C724.2 68.02,31.05 R732.1
UNNAMED_8_CAP_I814_N2: length 2.1
  BOTTOM w0.762: R733.1 68.45,22.69 C727.2
UNNAMED_8_CAP_I872_N2: length 2.2
  BOTTOM w0.762: R737.1 C731.2
UNNAMED_8_CAP_I936_N2: length 3.5
  BOTTOM w0.762: C729.2 106.75,30.59 108.45,28.9 R734.1
UNNAMED_8_CAP_I967_N1: length 2
  BOTTOM w0.508: R729.2 98.69,17.06 99.2,17.56 C720.1
UNNAMED_8_CAP_I970_N1: length 2.1
  BOTTOM w0.508: C718.1 99.2,32.83 98.72,33.31 R725.2
UNNAMED_8_CAP_I971_N1: length 2
  BOTTOM w0.508: R721.2 75.93,15.74 76.34,16.14 C716.1
UNNAMED_8_CAP_I974_N1: length 2
  BOTTOM w0.508: C714.1 76.09,31.74 75.68,32.14 R715.2
UNNAMED_8_CAP_I985_N2: length 1
  BOTTOM w0.381: C704.2 R704.1
UNNAMED_8_CAP_I986_N2: length 1
  BOTTOM w0.381: C706.2 R707.1
UNNAMED_8_CAP_I989_N2: length 1
  BOTTOM w0.394: R708.1 C708.2
UNNAMED_8_CAP_I990_N2: length 1
  BOTTOM w0.394: R711.1 C710.2
UNNAMED_8_CN2P_I1027_N1: length 5.3
  TOP w0.508: 111.2,20.94 P701.1 ; P701.1 109.86,22.27 ; P701.1 111.2,23.61 ; P701.1 112.53,22.27
UNNAMED_8_DIOLED_I983_N: length 1.9
  TOP w0.203: DS701.C 123.2,14.17 R701.2
UNNAMED_8_DIOLED_I1004_P: length 1.9
  TOP w0.508: R735.2 DS702.A
UNNAMED_9_CAP_I337_N1: length 1.5
  TOP w0.203: v2(142.91,47.88) 142.91,48.02 C801.1
  BOTTOM w0.203: v2(142.91,47.88) P801.B20
UNNAMED_9_CAP_I338_N1: length 1.7
  TOP w0.203: C802.1 142.2,48.37 v2(141.67,47.84)
  BOTTOM w0.203: P801.B21 141.68,47.84
  BOTTOM w0.394: 141.68,47.84 v2(141.67,47.84)
UNNAMED_9_CAP_I852_N2: length 1.4
  TOP w0.203: C806.2 139.12,68.54 v2(139.12,68.22)
  BOTTOM w0.203: P801.D5 139.74,67.6 v2(139.12,68.22)
UNNAMED_9_CAP_I853_N2: length 1.5
  TOP w0.203: v2(140.36,68.17) 140.36,68.55 C805.2
  BOTTOM w0.203: v2(140.36,68.17) 139.74,68.8 P801.D4
UNNAMED_9_CN400PAK_I293_N2: length 1.5
  TOP w0.305: R801.2 133.69,71.07 v2(134.02,70.74)
  BOTTOM w0.203: v2(134.02,70.74) P801.H2
UNNAMED_9_CN400PAK_I293_N10: length 1.5
  TOP w0.394: R802.2 v2(135.29,60.58)
  BOTTOM w0.203: P801.H10 v2(135.29,60.58)
UNNAMED_9_CN400PAK_I293_N11: length 1.5
  TOP w0.394: R803.2 v2(135.29,59.31)
  BOTTOM w0.203: v2(135.29,59.31) P801.H11
UNNAMED_9_CN400PAK_I293_N13: length 1.5
  TOP w0.394: R804.2 v2(134.02,56.77)
  BOTTOM w0.203: v2(134.02,56.77) P801.H13
UNNAMED_9_CN400PAK_I293_N14: length 1.5
  TOP w0.394: R805.2 v2(135.29,56.77)
  BOTTOM w0.203: P801.H14 v2(135.29,56.77)
UNNAMED_9_CN400PAK_I296_N12: length 1.6
  TOP w0.203: R806.2 135.43,58.18 v2(135.29,58.04)
  BOTTOM w0.203: P801.G12 v2(135.29,58.04)
UNNAMED_9_CN400PAK_I297_N18: length 75.8
  L8_SIG w0.114: v1(74.76,61.54) 74.94,61.72 74.94,62.98 75.57,63.61 85.54,63.61 86.75,62.4 96.66,62.4 106.91,52.15 135.23,52.15 136.21,51.17 136.84,51.17 137.59,50.42 v2(141.64,50.42)
  BOTTOM w0.203: v2(141.64,50.42) P801.C18 ; R816.2 74.3,61.29 74.56,61.54 v1(74.76,61.54)
UNNAMED_9_CN400PAK_I297_N19: length 71.5
  L8_SIG w0.114: v2(141.64,49.15) 141.07,49.72 130.93,49.72 130.09,50.56 128.5,50.56 128.15,50.21 127.38,50.21 127.37,50.2 126.95,50.2 126.94,50.21 126.12,50.21 125.49,50.85 104.66,50.85 94.5,61.01 77.86,61.01 v1(77.33,61.54)
  BOTTOM w0.203: v2(141.64,49.15) P801.C19 ; R817.2 76.84,61.06 v1(77.33,61.54)
UNNAMED_9_CN400PAK_I298_N11: length 1.6
  TOP w0.394: v2(140.37,59.31) 140.68,59.61 R810.2
  BOTTOM w0.203: P801.D11 v2(140.37,59.31)
UNNAMED_9_CN400PAK_I298_N14: length 1.5
  TOP w0.305: R811.2 140.38,55.49 v2(140.37,55.5)
  BOTTOM w0.203: P801.D14 v2(140.37,55.5)
UNNAMED_9_CN400PAK_I298_N15: length 1.5
  TOP w0.305: R812.2 140.38,54.22 v2(140.37,54.23)
  BOTTOM w0.203: P801.D15 v2(140.37,54.23)
UNNAMED_9_CN400PAK_I298_N17: length 72.3
  L8_SIG w0.114: v2(139.1,52.96) 137.34,54.72 108.76,54.72 97.72,65.76 97.72,65.78 96.66,66.85 83.83,66.85 83.07,67.61 76.16,67.61 v1(74.96,66.42)
  BOTTOM w0.203: R813.2 v1(74.96,66.42) ; v2(139.1,52.96) P801.D17
UNNAMED_9_CN400PAK_I298_N18: length 69.3
  L8_SIG w0.114: v1(77.56,66.32) 77.59,66.34 95.26,66.34 107.96,53.64 123.26,53.64 123.27,53.65 123.7,53.65 123.71,53.64 136.28,53.64 138.23,51.69 v2(139.1,51.69)
  BOTTOM w0.203: v1(77.56,66.32) 77.46,66.42 R814.2 ; v2(139.1,51.69) P801.D18
UNNAMED_9_CN400PAK_I299_N1: length 3.2
  TOP w0.394: R807.2 135.12,74.72 v2(136.56,73.28)
  BOTTOM w0.394: P801.F1 v2(136.56,73.28)
UNNAMED_9_ICM24CXX_I809_E2: length 4.1
  TOP w0.305: U801.3 116.5,30.65 116.07,30.21 115.97,30.21 115.63,29.87 R823.2 R822.1
VCON: length 5.5
  BOTTOM w0.394: Y401.1 Y403.1 Y402.1 C404.1 123.61,76.5 123.62,76.52 R407.2
VCXO_CTRL: length 42
  L5_SIG w0.114: v1(126.07,76.52) 111.53,76.52 103.19,68.17 90.46,68.17 v1(89.88,67.59)
  BOTTOM w0.254: U401.8 90.04,68.13 90.04,67.75 v1(89.88,67.59)
  BOTTOM w0.394: R407.1 v1(126.07,76.52)
VCXO_IN+: length 15.8
  L10_SIG w0.091: v1(95.63,64.79) 95.63,63.49 95.3,63.17 90.33,63.17 89.83,62.66 88.51,62.66 88.42,62.76 88.42,63.01 v1(88.76,63.36)
  BOTTOM w0.203: U401.11 88.54,68.07 88.54,67.78 88.47,67.71 88.47,63.65 v1(88.76,63.36) ; C409.2 v1(95.63,64.79)
VCXO_IN-: length 15.8
  L10_SIG w0.091: v1(87.74,63.36) 88.16,62.94 88.16,62.65 88.4,62.41 89.93,62.41 90.43,62.91 95.36,62.91 95.63,62.65 v1(95.63,61.79)
  BOTTOM w0.203: v1(87.74,63.36) 88.11,63.73 88.11,67.71 88.04,67.78 88.04,68 U401.12 ; C407.2 v1(95.63,61.79)
VOUT1_1V3_ANLG: length 82.1
  TOP w0.305: R612.1 44.08,29.52 44.08,30.91 42.55,32.44 v1(41.67,32.44)
  TOP w0.508: P703.1 77.6,28.16 82.18,32.74 R716.2
  TOP w0.762: C602.1 63.45,29.76 P703.1 65.23,27.99 C601.1
  L8_SIG w0.508: 65.06,27.08 P703.1 ; P703.1 65.06,29.24 ; P703.1 66.14,28.16 ; P703.1 63.98,28.16
  L12_PWR w0.394: v4(27.5,32.78) 27.5,32.21 29.31,30.41 29.31,29.99 29.47,29.83 29.47,27.73
  BOTTOM w0.305: v1(41.67,32.44) 41.78,32.33 ; E603.1 42.43,41.7 42,41.7 v4(41.87,41.58)
  BOTTOM w0.394: v1(11.95,56.69) 11.19,55.93 11.19,55.42 E611.1 ; v4(27.5,32.78) 27.8,32.78 28.71,33.69 28.71,33.84 ; v4(36.45,39.41) v4(35.95,38.91) 35.95,38.79 v4(35.57,38.41) ; E608.1 v1(12.71,50.85) ; E612.1 v1(10.04,62.78) ; 54.01,29.67 54.43,29.25 54.43,28.69 52.71,26.97 R601.1 ; E607.1 v1(9.03,42.97) ; E610.1 v1(10.03,59.79)
  BOTTOM w0.508: E605.1 15.44,39.86 v1(15.44,38.59) ; R614.2 v4(35.57,38.41) ; v1(31.92,28.24) v1(31.92,27.48) ; P703.1 65.06,29.24 ; P703.1 65.06,27.08 ; P703.1 63.98,28.16 ; P703.1 66.14,28.16 ; 41.76,32.33 43.85,32.33 44.6,33.08 E606.1 ; E604.1 v1(44.56,39.49) ; E609.1 v1(21.22,28.75)
  BOTTOM w0.762: E613.1 59.73,29.67 ; E601.1 54.01,29.67
  vias: v1(40.99,32.44) v1(41,33.1) v1(41.67,33.1) v1(61.35,28.49) v1(61.35,27.73) v1(62.24,28.49) v1(62.24,27.73) v1(63.13,28.49) v1(63.13,27.73)
VOUT2_1V3_DIG: length 110
  TOP w0.254: v2(37.24,46.78) U101.L8 v2(37.24,47.58) U101.L9 v2(37.24,48.38)
  TOP w0.305: P704.1 64.24,23.04 R604.1
  TOP w0.508: R723.2 71.64,17.92 v1(70.65,18.91) v1(69.76,18.91) v1(68.87,18.91) v1(67.98,18.91) v1(67.98,19.67) v1(68.87,19.67) v1(69.76,19.67) v1(70.65,19.67)
  TOP w1.27: C638.1 65.12,22.27 P704.1
  L5_SIG w0.508: 66.14,22.21 P704.1 65.06,21.13
  L5_SIG w1.905: v1(48.27,32.94) v1(47.21,32.94) v1(47.21,32.03) 47.74,32.56 51.95,32.56 55.25,29.26 56.52,29.26 63.57,22.21 P704.1
  L8_SIG w0.508: 65.06,21.13 P704.1 ; P704.1 63.98,22.21 ; P704.1 65.06,23.29 ; P704.1 66.14,22.21
  L12_PWR w0.635: v2(37.24,47.58) v2(37.24,48.38)
  L12_PWR w1.016: v2(37.24,47.58) v2(37.24,46.78) 38.25,45.77 40.27,45.77
  L12_PWR w1.27: 40.27,45.77 41.16,44.88 46.23,44.88 48.9,42.21 48.9,40.31 49.16,40.05
  L12_PWR w1.905: v1(48.27,32.94) v1(47.21,32.94) v1(47.21,32.03) 48.25,32.03 v1(48.27,32.05) v1(48.27,32.94) ; v1(48.27,32.94) 49.16,33.83 49.16,40.05
  BOTTOM w0.305: C636.1 37.86,45.98 C637.1 37.55,47.08 v2(37.24,46.78) v2(37.24,47.58) v2(37.24,48.38)
  BOTTOM w0.508: 66.14,22.21 P704.1 65.06,21.13
  BOTTOM w1.27: C639.1 65,22.27 P704.1 66.5,20.78 C727.1
VOUT3_3V3: length 117.9
  TOP w0.254: v2(29.24,52.38) U101.B14
  TOP w0.305: R608.1 v1(50.43,30.4)
  TOP w0.394: v2(133.42,74.98) R807.1
  TOP w0.508: R727.2 98.73,32.87 99.61,31.99 v1(101.51,31.99) v1(102.27,31.99) ; P705.1 103.42,32.37 v1(103.04,31.99) R735.1
  L3_PWR w0.508: P705.1 104.5,34.18 ; P705.1 103.42,35.26 ; P705.1 102.34,34.18 ; P705.1 103.42,33.1
  L10_SIG w0.203: v1(50.43,30.4) 51.33,29.51 55.38,29.51 59.45,25.45 v1(59.45,21.38)
  L12_PWR w0.394: v2(133.42,74.98) 133.99,74.98 135.09,73.88 135.54,73.88 135.9,73.53 135.9,73.07 139.76,69.21 139.76,67.18 140.98,65.96 140.98,44.75 138.36,42.13 136.31,42.13 134.69,40.51 134.69,40.07 130.01,35.39 122.27,35.39 120.53,37.13 115.07,37.13 114.46,36.52 111.28,36.52 106.76,31.99 v1(103.04,31.99) v1(102.27,31.99) v1(101.51,31.99)
  BOTTOM w0.305: C641.1 29.56,52.05 v2(29.24,52.38)
  BOTTOM w0.508: 103.42,33.1 P705.1 ; P705.1 104.5,34.18 ; P705.1 102.34,34.18 ; P705.1 103.42,35.27 103.39,35.3 103.39,35.89 103.45,35.94 E706.1
  vias: v1(57.41,21.38) v1(58.43,21.38) v1(58.47,20.11) v1(58.94,20.75) v1(59.45,20.11)
VOUT4_1V8: length 80.9
  TOP w0.203: v5(30.08,49.18) 30.84,49.18 ; 37.35,38.48 C315.1
  TOP w0.254: 30.84,49.18 U101.D10
  TOP w0.394: L316.1 32.27,39.26 C316.1 v1(32.27,37.85) ; 32.27,55 32.27,54.29 L307.2 ; 32.27,55 v1(32.27,56.05) ; 32.27,55 C307.1 ; 37.41,38.41 37.41,39.26 L315.2 ; 37.41,38.41 v1(37.41,37.85) ; 37.41,38.41 37.35,38.48 ; v1(37.42,56.04) 37.41,56.02 C308.1 37.41,54.29 L308.1 ; v1(42.06,38.18) 42.61,38.18 v1(42.62,38.19) 43.17,38.19 v1(43.18,38.19) 44.84,36.53 44.84,32.56 47.13,30.27 47.13,29.52 R610.1
  TOP w0.508: v1(102.88,18.28) v1(102.17,18.28) v1(101.49,18.28) 96.26,18.28 95.36,19.18 R731.2
  L3_PWR w0.203: 28.02,48.76 29.66,48.76 v5(30.08,49.18)
  L3_PWR w0.305: v1(32.27,56.05) 32.41,55.91 37.26,55.91 37.39,56.04 v1(37.42,56.04)
  L3_PWR w0.394: v1(37.41,37.85) 36.97,37.85 36.76,37.64 32.48,37.64 v1(32.27,37.85)
  L3_PWR w0.508: P706.1 103.42,17.32 ; P706.1 102.34,16.24 ; P706.1 104.5,16.24 ; P706.1 103.42,15.16
  L3_PWR w0.762: 33.41,68.63 33.41,68.66 33.66,68.91 33.76,68.82 34.74,68.82 35.44,68.12 35.44,62.56 36.21,61.79 36.38,61.79 36.89,61.28 36.89,60.55 34.81,58.47 34.81,55.91 ; 38.33,32.21 38.33,32.78 34.81,36.31 34.81,37.64
  BOTTOM w0.305: C640.1 30.22,49.32 v5(30.08,49.18)
  BOTTOM w0.508: 103.42,15.16 P706.1 ; P706.1 102.34,16.24 ; P706.1 104.5,16.24 ; P706.1 103.42,17.32 ; v1(31.39,70.44) v1(32.1,70.44) 32.83,70.44 ; C320.1 32.5,69.83 32.81,70.15 32.81,70.43 32.83,70.44 ; 32.83,70.44 v1(32.85,70.44) ; 42.68,37.45 42.73,37.4 42.44,37.11

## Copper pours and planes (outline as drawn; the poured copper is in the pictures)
AGND on TOP: 0,12.7 0,33.81 0.62,33.81 0.83,34.2 0.82,36.41 0.62,36.8 0,36.8 0,57.69 0.62,57.69 0.83,58.07 0.82,60.29 0.62,60.67 0,60.68 0,81.79 32.45,81.79 32.45,81.16 32.83,80.96 35.05,80.97 35.43,81.17 35.44,81.79 148.44,81.79 148.44,12.7 37.23,12.7 37.23,13.32 36.84,13.53 34.63,13.52 34.24,13.32 34.24,12.7 ; 8 cut-outs
AGND on BOTTOM: 0,12.7 0,21.87 0.58,21.87 0.79,22.26 0.78,24.48 0.58,24.86 0,24.86 0,45.75 0.58,45.75 0.79,46.13 0.78,48.35 0.58,48.73 0,48.74 0,69.63 0.58,69.63 0.79,70.01 0.78,72.23 0.58,72.61 0,72.61 0,81.79 20.39,81.79 20.39,81.21 20.77,81 22.99,81.01 23.37,81.21 23.38,81.79 148.44,81.79 148.44,12.7 23.38,12.7 23.38,13.28 22.99,13.49 20.77,13.48 20.39,13.28 20.39,12.7 ; 9 cut-outs
AGND on L2_GND: 0,12.7 0,81.79 148.44,81.79 148.44,12.7 ; 2 cut-outs
AGND on L3_PWR: 0,12.7 0,81.79 148.44,81.79 148.44,12.7 ; 1 cut-out
AGND on L4_GND, L6_GND, L9_GND, L11_GND, L12_PWR, L13_GND: 0,12.7 0,81.79 148.44,81.79 148.44,12.7
AGND on L5_SIG: 0,12.7 0,81.79 148.44,81.79 148.44,12.7 ; 31 cut-outs
AGND on L7_SIG: 0,12.7 0,81.79 148.44,81.79 148.44,12.7 ; 17 cut-outs
